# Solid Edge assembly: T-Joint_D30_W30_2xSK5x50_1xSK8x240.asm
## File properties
Author: fknapp
Template: iso metric assembly.asm
Last saved by: fknapp
Revision: 7
Application: Solid Edge
Username: fknapp
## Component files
T-Joint_D30_W30.par
SK Knapp Schraube 8x240_ohne_Gewinde_22042020.par
SK Schraube 5x50_ohne_Gewinde.par
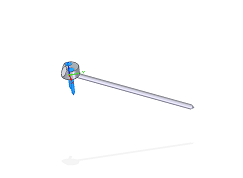
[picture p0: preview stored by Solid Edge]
